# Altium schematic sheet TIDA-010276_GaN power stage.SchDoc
size 431 x 279 mm; Date: Not shown in title block; ApprovedBy: Not shown in title block; CheckedBy: Not shown in title block; Author: Not shown in title block; CompanyName: Not shown in title block; DrawnBy: Jenson Fang; Engineer: Jenson Fang; Organization: Not shown in title block; Address1: Not shown in title block; Address2: Not shown in title block; Address3: Not shown in title block; Address4: Not shown in title block; DocumentNumber: 2; Revision: Use project parameter SCH_Rev; SheetNumber: 2; SheetTotal: 6; PageSetup: Record=PageOptions¦CenterHorizontal=True¦CenterVertical=True¦PrintScale=1.00¦XCorrection=1.00¦YCorrection=1.00¦PrintKind=0¦BorderSize=5000000¦LeftOffset=0¦BottomOffset=0¦Orientation=2¦PaperLength=1000¦PaperWidth=1000¦Scale=100¦PaperSource=15¦PrintQuality=600¦MediaType=1¦DitherType=10¦PaperKind=Letter¦PrintScaleMode=1
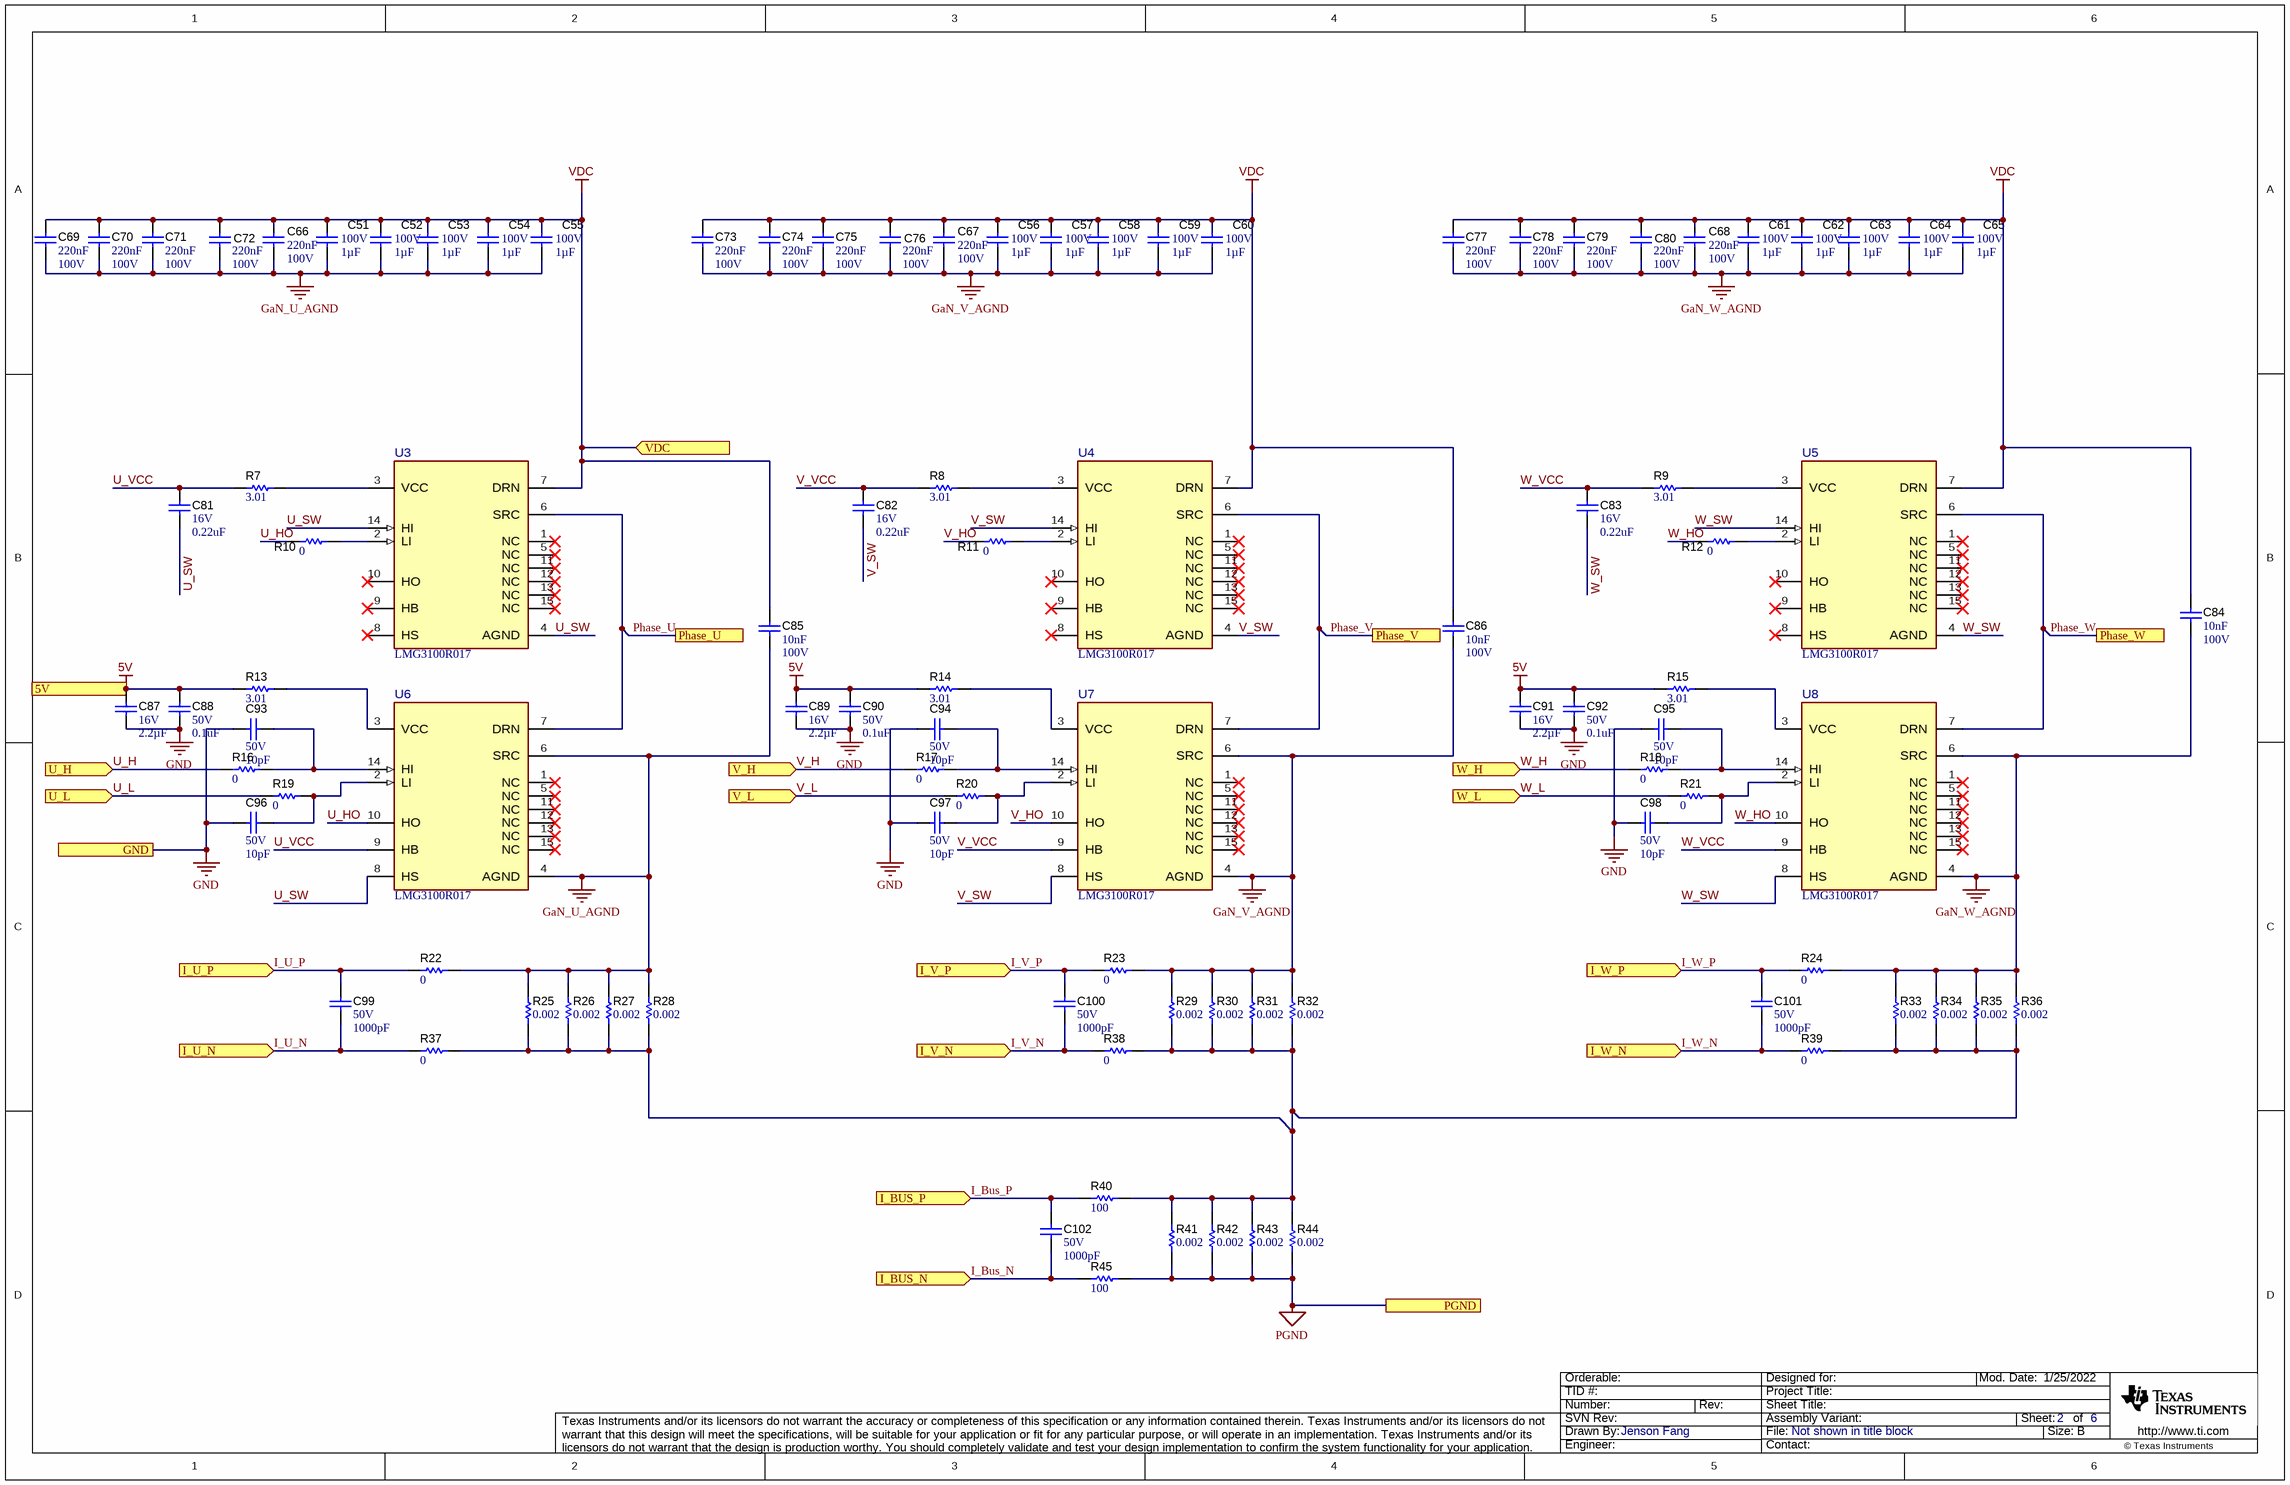
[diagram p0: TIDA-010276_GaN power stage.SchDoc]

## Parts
C51  VDC_V: 100V  ValueDisplayed: 1µF  [0805_HV]  (hidden comment: C2012X7S2A105K125AE)
C52  VDC_V: 100V  ValueDisplayed: 1µF  [0805_HV]  (hidden comment: C2012X7S2A105K125AE)
C53  VDC_V: 100V  ValueDisplayed: 1µF  [0805_HV]  (hidden comment: C2012X7S2A105K125AE)
C54  VDC_V: 100V  ValueDisplayed: 1µF  [0805_HV]  (hidden comment: C2012X7S2A105K125AE)
C55  VDC_V: 100V  ValueDisplayed: 1µF  [0805_HV]  (hidden comment: C2012X7S2A105K125AE)
C56  VDC_V: 100V  ValueDisplayed: 1µF  [0805_HV]  (hidden comment: C2012X7S2A105K125AE)
C57  VDC_V: 100V  ValueDisplayed: 1µF  [0805_HV]  (hidden comment: C2012X7S2A105K125AE)
C58  VDC_V: 100V  ValueDisplayed: 1µF  [0805_HV]  (hidden comment: C2012X7S2A105K125AE)
C59  VDC_V: 100V  ValueDisplayed: 1µF  [0805_HV]  (hidden comment: C2012X7S2A105K125AE)
C60  VDC_V: 100V  ValueDisplayed: 1µF  [0805_HV]  (hidden comment: C2012X7S2A105K125AE)
C61  VDC_V: 100V  ValueDisplayed: 1µF  [0805_HV]  (hidden comment: C2012X7S2A105K125AE)
C62  VDC_V: 100V  ValueDisplayed: 1µF  [0805_HV]  (hidden comment: C2012X7S2A105K125AE)
C63  VDC_V: 100V  ValueDisplayed: 1µF  [0805_HV]  (hidden comment: C2012X7S2A105K125AE)
C64  VDC_V: 100V  ValueDisplayed: 1µF  [0805_HV]  (hidden comment: C2012X7S2A105K125AE)
C65  VDC_V: 100V  ValueDisplayed: 1µF  [0805_HV]  (hidden comment: C2012X7S2A105K125AE)
C66  Cap_F: 220nF  VDC_V: 100V  [0603]  (hidden comment: HMK107C7224KAHTE)
C67  Cap_F: 220nF  VDC_V: 100V  [0603]  (hidden comment: HMK107C7224KAHTE)
C68  Cap_F: 220nF  VDC_V: 100V  [0603]  (hidden comment: HMK107C7224KAHTE)
C69  Cap_F: 220nF  VDC_V: 100V  [0603]  (hidden comment: HMK107C7224KAHTE)
C70  Cap_F: 220nF  VDC_V: 100V  [0603]  (hidden comment: HMK107C7224KAHTE)
C71  Cap_F: 220nF  VDC_V: 100V  [0603]  (hidden comment: HMK107C7224KAHTE)
C72  Cap_F: 220nF  VDC_V: 100V  [0603]  (hidden comment: HMK107C7224KAHTE)
C73  Cap_F: 220nF  VDC_V: 100V  [0603]  (hidden comment: HMK107C7224KAHTE)
C74  Cap_F: 220nF  VDC_V: 100V  [0603]  (hidden comment: HMK107C7224KAHTE)
C75  Cap_F: 220nF  VDC_V: 100V  [0603]  (hidden comment: HMK107C7224KAHTE)
C76  Cap_F: 220nF  VDC_V: 100V  [0603]  (hidden comment: HMK107C7224KAHTE)
C77  Cap_F: 220nF  VDC_V: 100V  [0603]  (hidden comment: HMK107C7224KAHTE)
C78  Cap_F: 220nF  VDC_V: 100V  [0603]  (hidden comment: HMK107C7224KAHTE)
C79  Cap_F: 220nF  VDC_V: 100V  [0603]  (hidden comment: HMK107C7224KAHTE)
C80  Cap_F: 220nF  VDC_V: 100V  [0603]  (hidden comment: HMK107C7224KAHTE)
C81  VDC_V: 16V  ValueDisplayed: 0.22uF  [0402]  (hidden comment: GRM155R71C224KA12D)
C82  VDC_V: 16V  ValueDisplayed: 0.22uF  [0402]  (hidden comment: GRM155R71C224KA12D)
C83  VDC_V: 16V  ValueDisplayed: 0.22uF  [0402]  (hidden comment: GRM155R71C224KA12D)
C84  Cap_F: 10nF  VDC_V: 100V  [0805_HV]  (hidden comment: GRM21BR72A103KA01L)
C85  Cap_F: 10nF  VDC_V: 100V  [0805_HV]  (hidden comment: GRM21BR72A103KA01L)
C86  Cap_F: 10nF  VDC_V: 100V  [0805_HV]  (hidden comment: GRM21BR72A103KA01L)
C87  VDC_V: 16V  Cap_F: 2.2µF  [0603]  (hidden comment: GRM188Z71C225KE43)
C88  VDC_V: 50V  ValueDisplayed: 0.1uF  [0402]  (hidden comment: GCM155R71H104KE02D)
C89  VDC_V: 16V  Cap_F: 2.2µF  [0603]  (hidden comment: GRM188Z71C225KE43)
C90  VDC_V: 50V  ValueDisplayed: 0.1uF  [0402]  (hidden comment: GCM155R71H104KE02D)
C91  VDC_V: 16V  Cap_F: 2.2µF  [0603]  (hidden comment: GRM188Z71C225KE43)
C92  VDC_V: 50V  ValueDisplayed: 0.1uF  [0402]  (hidden comment: GCM155R71H104KE02D)
C93  VDC_V: 50V  ValueDisplayed: 10pF  [0402]  (hidden comment: GRM1555C1H100JA01D)
C94  VDC_V: 50V  ValueDisplayed: 10pF  [0402]  (hidden comment: GRM1555C1H100JA01D)
C95  VDC_V: 50V  ValueDisplayed: 10pF  [0402]  (hidden comment: GRM1555C1H100JA01D)
C96  VDC_V: 50V  ValueDisplayed: 10pF  [0402]  (hidden comment: GRM1555C1H100JA01D)
C97  VDC_V: 50V  ValueDisplayed: 10pF  [0402]  (hidden comment: GRM1555C1H100JA01D)
C98  VDC_V: 50V  ValueDisplayed: 10pF  [0402]  (hidden comment: GRM1555C1H100JA01D)
C99  VDC_V: 50V  ValueDisplayed: 1000pF  [0402]  (hidden comment: GRM1555C1H102FA01D)
C100  VDC_V: 50V  ValueDisplayed: 1000pF  [0402]  (hidden comment: GRM1555C1H102FA01D)
C101  VDC_V: 50V  ValueDisplayed: 1000pF  [0402]  (hidden comment: GRM1555C1H102FA01D)
C102  VDC_V: 50V  ValueDisplayed: 1000pF  [0402]  (hidden comment: GRM1555C1H102FA01D)
R7  ValueDisplayed: 3.01  [0402]  (hidden comment: CRCW04023R01FKED)
R8  ValueDisplayed: 3.01  [0402]  (hidden comment: CRCW04023R01FKED)
R9  ValueDisplayed: 3.01  [0402]  (hidden comment: CRCW04023R01FKED)
R10  ValueDisplayed: 0  [0402]  (hidden comment: RC0402JR-070RL)
R11  ValueDisplayed: 0  [0402]  (hidden comment: RC0402JR-070RL)
R12  ValueDisplayed: 0  [0402]  (hidden comment: RC0402JR-070RL)
R13  ValueDisplayed: 3.01  [0402]  (hidden comment: CRCW04023R01FKED)
R14  ValueDisplayed: 3.01  [0402]  (hidden comment: CRCW04023R01FKED)
R15  ValueDisplayed: 3.01  [0402]  (hidden comment: CRCW04023R01FKED)
R16  ValueDisplayed: 0  [0603]  (hidden comment: PMR03EZPJ000)
R17  ValueDisplayed: 0  [0603]  (hidden comment: PMR03EZPJ000)
R18  ValueDisplayed: 0  [0603]  (hidden comment: PMR03EZPJ000)
R19  ValueDisplayed: 0  [0603]  (hidden comment: PMR03EZPJ000)
R20  ValueDisplayed: 0  [0603]  (hidden comment: PMR03EZPJ000)
R21  ValueDisplayed: 0  [0603]  (hidden comment: PMR03EZPJ000)
R22  ValueDisplayed: 0  [0603]  (hidden comment: PMR03EZPJ000)
R23  ValueDisplayed: 0  [0603]  (hidden comment: PMR03EZPJ000)
R24  ValueDisplayed: 0  [0603]  (hidden comment: PMR03EZPJ000)
R25  ValueDisplayed: 0.002  [1206]  (hidden comment: CRF1206-FZ-R002ELF)
R26  ValueDisplayed: 0.002  [1206]  (hidden comment: CRF1206-FZ-R002ELF)
R27  ValueDisplayed: 0.002  [1206]  (hidden comment: CRF1206-FZ-R002ELF)
R28  ValueDisplayed: 0.002  [1206]  (hidden comment: CRF1206-FZ-R002ELF)
R29  ValueDisplayed: 0.002  [1206]  (hidden comment: CRF1206-FZ-R002ELF)
R30  ValueDisplayed: 0.002  [1206]  (hidden comment: CRF1206-FZ-R002ELF)
R31  ValueDisplayed: 0.002  [1206]  (hidden comment: CRF1206-FZ-R002ELF)
R32  ValueDisplayed: 0.002  [1206]  (hidden comment: CRF1206-FZ-R002ELF)
R33  ValueDisplayed: 0.002  [1206]  (hidden comment: CRF1206-FZ-R002ELF)
R34  ValueDisplayed: 0.002  [1206]  (hidden comment: CRF1206-FZ-R002ELF)
R35  ValueDisplayed: 0.002  [1206]  (hidden comment: CRF1206-FZ-R002ELF)
R36  ValueDisplayed: 0.002  [1206]  (hidden comment: CRF1206-FZ-R002ELF)
R37  ValueDisplayed: 0  [0603]  (hidden comment: PMR03EZPJ000)
R38  ValueDisplayed: 0  [0603]  (hidden comment: PMR03EZPJ000)
R39  ValueDisplayed: 0  [0603]  (hidden comment: PMR03EZPJ000)
R40  ValueDisplayed: 100  [0402]  (hidden comment: CRCW0402100RJNED)
R41  ValueDisplayed: 0.002  [1206]  (hidden comment: CRF1206-FZ-R002ELF)
R42  ValueDisplayed: 0.002  [1206]  (hidden comment: CRF1206-FZ-R002ELF)
R43  ValueDisplayed: 0.002  [1206]  (hidden comment: CRF1206-FZ-R002ELF)
R44  ValueDisplayed: 0.002  [1206]  (hidden comment: CRF1206-FZ-R002ELF)
R45  ValueDisplayed: 100  [0402]  (hidden comment: CRCW0402100RJNED)
U3  LMG3100R017  [VBE0015A-MFG]
U4  LMG3100R017  [VBE0015A-MFG]
U5  LMG3100R017  [VBE0015A-MFG]
U6  LMG3100R017  [VBE0015A-MFG]
U7  LMG3100R017  [VBE0015A-MFG]
U8  LMG3100R017  [VBE0015A-MFG]

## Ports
5V, GND, I_BUS_N (in), I_BUS_P (in), I_U_N (in), I_U_P (in), I_V_N (in), I_V_P (in), I_W_N (in), I_W_P (in), PGND, Phase_U, Phase_V, Phase_W, U_H (in), U_L (in), V_H (in), V_L (in), VDC (in), W_H (in), W_L (in)

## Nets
5V: C87.1 C88.1 C89.1 C90.1 C91.1 C92.1 R13.1 R14.1 R15.1 ; port 5V
GaN_U_AGND: C51.2 C52.2 C53.2 C54.2 C55.2 C66.2 C69.2 C70.2 C71.2 C72.2 C85.2 R22.1 R25.2 R26.2 R27.2 R28.2 U6.4(AGND) U6.6(SRC)
GaN_V_AGND: C56.2 C57.2 C58.2 C59.2 C60.2 C67.2 C73.2 C74.2 C75.2 C76.2 C86.2 R23.1 R29.2 R30.2 R31.2 R32.2 U7.4(AGND) U7.6(SRC)
GaN_W_AGND: C61.2 C62.2 C63.2 C64.2 C65.2 C68.2 C77.2 C78.2 C79.2 C80.2 C84.2 R24.1 R33.2 R34.2 R35.2 R36.2 U8.4(AGND) U8.6(SRC)
GND: C87.2 C88.2 C89.2 C90.2 C91.2 C92.2 C93.2 C94.2 C95.2 C96.2 C97.2 C98.2 ; port GND
PGND: R41.1 R42.1 R43.1 R44.1 R45.2 ; port PGND
VDC: C51.1 C52.1 C53.1 C54.1 C55.1 C56.1 C57.1 C58.1 C59.1 C60.1 C61.1 C62.1 C63.1 C64.1 C65.1 C66.1 C67.1 C68.1 C69.1 C70.1 C71.1 C72.1 C73.1 C74.1 C75.1 C76.1 C77.1 C78.1 C79.1 C80.1 C84.1 C85.1 C86.1 U3.7(DRN) U4.7(DRN) U5.7(DRN) ; port VDC
I_Bus_N: C102.2 R45.1 ; port I_BUS_N
I_Bus_P: C102.1 R40.1 ; port I_BUS_P
I_U_N: C99.2 R37.2 ; port I_U_N
I_U_P: C99.1 R22.2 ; port I_U_P
I_V_N: C100.2 R38.2 ; port I_V_N
I_V_P: C100.1 R23.2 ; port I_V_P
I_W_N: C101.2 R39.2 ; port I_W_N
I_W_P: C101.1 R24.2 ; port I_W_P
Phase_U: U3.6(SRC) U6.7(DRN) ; port Phase_U
Phase_V: U4.6(SRC) U7.7(DRN) ; port Phase_V
Phase_W: U5.6(SRC) U8.7(DRN) ; port Phase_W
U_H: R16.2 ; port U_H
U_HO: R10.1 U6.10(HO)
U_L: R19.2 ; port U_L
U_SW: C81.2 U3.4(AGND) U3.14(HI) U6.8(HS)
U_VCC: C81.1 R7.1 U6.9(HB)
V_H: R17.2 ; port V_H
V_HO: R11.1 U7.10(HO)
V_L: R20.2 ; port V_L
V_SW: C82.2 U4.4(AGND) U4.14(HI) U7.8(HS)
V_VCC: C82.1 R8.1 U7.9(HB)
W_H: R18.2 ; port W_H
W_HO: R12.1 U8.10(HO)
W_L: R21.2 ; port W_L
W_SW: C83.2 U5.4(AGND) U5.14(HI) U8.8(HS)
W_VCC: C83.1 R9.1 U8.9(HB)
NetC93_1: C93.1 R16.1 U6.14(HI)
NetC94_1: C94.1 R17.1 U7.14(HI)
NetC95_1: C95.1 R18.1 U8.14(HI)
NetC96_1: C96.1 R19.1 U6.2(LI)
NetC97_1: C97.1 R20.1 U7.2(LI)
NetC98_1: C98.1 R21.1 U8.2(LI)
NetR7_2: R7.2 U3.3(VCC)
NetR8_2: R8.2 U4.3(VCC)
NetR9_2: R9.2 U5.3(VCC)
NetR10_2: R10.2 U3.2(LI)
NetR11_2: R11.2 U4.2(LI)
NetR12_2: R12.2 U5.2(LI)
NetR13_2: R13.2 U6.3(VCC)
NetR14_2: R14.2 U7.3(VCC)
NetR15_2: R15.2 U8.3(VCC)
NetR25_1: R25.1 R26.1 R27.1 R28.1 R29.1 R30.1 R31.1 R32.1 R33.1 R34.1 R35.1 R36.1 R37.1 R38.1 R39.1 R40.2 R41.2 R42.2 R43.2 R44.2

Not connected (* = marked no-connect by the designer): U3 1(NC)* 5(NC)* 8(HS)* 9(HB)* 10(HO)* 11(NC)* 12(NC)* 13(NC)* 15(NC)*; U4 1(NC)* 5(NC)* 8(HS)* 9(HB)* 10(HO)* 11(NC)* 12(NC)* 13(NC)* 15(NC)*; U5 1(NC)* 5(NC)* 8(HS)* 9(HB)* 10(HO)* 11(NC)* 12(NC)* 13(NC)* 15(NC)*; U6 1(NC)* 5(NC)* 11(NC)* 12(NC)* 13(NC)* 15(NC)*; U7 1(NC)* 5(NC)* 11(NC)* 12(NC)* 13(NC)* 15(NC)*; U8 1(NC)* 5(NC)* 11(NC)* 12(NC)* 13(NC)* 15(NC)*

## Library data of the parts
C51-C65 = CMP-0750059-1: CAP, CERM, 1 µF, 100 V,+/- 10%, X7S, 0805; Manufacturer: TDK; TaMax_C: 125°C; SizeAreaWB_mm2: 6.75; SizeY_mm: 1.25; Green_REACh: Incomplete; TaMin_C: -55°C; Cap_Case: 0805; SizeZ_mm: 1.45; U/M: EA; SizeX_mm: 2; Polarized: N; Green_Lifecycle: Active; SizeArea_mm2: 2.5; Value: 1uF; AEC Category: Q200
C66-C80 = CMP-0077894-3: CAP, CERM, 0.22 µF, 100 V,+/- 10%, X7S, AEC-Q200 Grade 1, 0603; Manufacturer: Taiyo Yuden; TaMin_C: -55°C; Polarized: N; SizeAreaWB_mm2: 4.68; U/M: EA; Value: 0.22uF; TaMax_C: 125°C; SizeZ_mm: 1.0; SizeX_mm: 1.6; SizeY_mm: 0.8; SizeArea_mm2: 1.28; AEC Qualified: Y; AEC Category: Q200; ValueDisplayed: 0.22µF; AEC Grade: 1
C81-C83 = CMP-0006648-1: CAP, CERM, 0.22 uF, 16 V, +/- 10%, X7R, 0402; Manufacturer: MuRata; TaMin_C: -55°C; Polarized: N; SizeAreaWB_mm2: 3; Value1: Unknown; U/M: EA; Value: 0.22uF; TaMax_C: 125°C; SizeZ_mm: 0.6; SizeX_mm: 1; SizeY_mm: 0.5; Cap_F: 220nF; AEC Category: Q200
C84-C86 = CMP-0008361-2: CAP, CERM, 0.01 uF, 100 V, +/- 10%, X7R, 0805; Manufacturer: MuRata; TaMin_C: -55°C; Polarized: N; SizeAreaWB_mm2: 6.75; Value1: Unknown; U/M: EA; Value: 0.01uF; TaMax_C: 125°C; SizeZ_mm: 1.45; SizeX_mm: 2; SizeY_mm: 1.25; Cap_Case: 0805; SizeArea_mm2: 2.5; AEC Category: Q200
C87 C89 C91 = CMP-0007499-1: CAP, CERM, 2.2 uF, 16 V, +/- 10%, X7R, 0603; Manufacturer: MuRata; TaMin_C: -55°C; Polarized: N; SizeAreaWB_mm2: 4.68; Value1: Unknown; U/M: EA; Value: 2.2uF; TaMax_C: 125°C; SizeZ_mm: 1; SizeX_mm: 1.6; SizeY_mm: 0.8; SizeArea_mm2: 1.28; AEC Category: Q200
C88 C90 C92 = CMP-0006356-2: CAP, CERM, 0.1 uF, 50 V, +/- 10%, X7R, AEC-Q200 Grade 1, 0402; Manufacturer: MuRata; TaMin_C: -55°C; Polarized: N; SizeAreaWB_mm2: 3; Value1: Unknown; U/M: EA; Value: 0.1uF; TaMax_C: 125°C; SizeZ_mm: 0.6; SizeX_mm: 1; SizeY_mm: 0.5; AEC Qualified: Y; Cap_F: 100nF; AEC Category: Q200
C93-C98 = CMP-0006408-2: CAP, CERM, 10 pF, 50 V, +/- 5%, C0G/NP0, 0402; Manufacturer: MuRata; TaMin_C: -55°C; Polarized: N; SizeAreaWB_mm2: 3; Value1: Unknown; U/M: EA; Value: 10pF; TaMax_C: 125°C; SizeZ_mm: 0.6; SizeX_mm: 1; SizeY_mm: 0.5; AEC Category: Q200
C99-C102 = CMP-0006411-2: CAP, CERM, 1000 pF, 50 V, +/- 1%, C0G/NP0, 0402; Manufacturer: MuRata; TaMin_C: -55°C; Polarized: N; SizeAreaWB_mm2: 3; Value1: Unknown; U/M: EA; Value: 1000pF; TaMax_C: 125°C; SizeZ_mm: 0.6; SizeX_mm: 1; SizeY_mm: 0.5; Cap_F: 1nF; AEC Category: Q200
R7-R9 R13-R15 = CMP-0026353-2: RES, 3.01, 1%, 0.063 W, AEC-Q200 Grade 0, 0402; Manufacturer: Vishay-Dale; Power_W: 63mW; TempCo: 100 ppm/C; Value_Code: 3R01; Value: 3.01; EIA_Code: E96; SizeX_mm: 1; SizeY_mm: 0.5; SizeZ_mm: 0.6; Value2: 0.063W; AEC Qualified: Y; VDC_V: 50V; AEC Category: Q200; AEC Grade: 0
R10-R12 = CMP-0027004-2: RES, 0, 5%, 0.063 W, 0402; Manufacturer: Yageo America; Power_W: 63mW; TempCo: 200 ppm/C; Value_Code: 0000; U/M: EA; Value: 0; EIA_Code: E24; SizeX_mm: 1; SizeY_mm: 0.5; SizeZ_mm: 0.6; Value2: 0.063W; VDC_V: 50V; AEC Category: Q200
R16-R24 R37-R39 = CMP-0086358-1: RES, 0, 0%, 0.25 W, AEC-Q200 Grade 0, 0603; Manufacturer: Rohm; Power_W: 250mW; SizeZ_mm: 1; SizeArea_mm2: 1.28; Value2: 0.25W; SizeAreaWB_mm2: 4.68; Value_Code: 0000; Value: 0; AEC Qualified: Y; AEC Category: Q200; SizeX_mm: 1.6; SizeY_mm: 0.8
R25-R36 R41-R44 = CMP-0078822-1: RES, 0.002, 1%, 1 W, AEC-Q200 Grade 0, 1206; Manufacturer: Bourns; Value_Code: 2L000; SizeArea_mm2: 5.12; AEC Qualified: Y; AEC Category: Q200; Res_ohm: 2m; Value: 0.002; SizeZ_mm: 1.35; TempCo: 50 ppm/C; AEC Grade: 0; SizeY_mm: 1.6; Power_W: 1W; SizeX_mm: 3.2
R40 R45 = CMP-0026824-3: RES, 100, 5%, 0.063 W, AEC-Q200 Grade 0, 0402; Manufacturer: Vishay-Dale; Power_W: 63mW; TempCo: 200 ppm/C; Value_Code: 100R; Value: 100; EIA_Code: E24; SizeX_mm: 1; SizeY_mm: 0.5; SizeZ_mm: 0.6; Value2: 0.063W; AEC Qualified: Y; VDC_V: 50V; AEC Category: Q200; AEC Grade: 0
U3-U8 = CMP-0037654-1: 100-V, 64-A GaN with Integrated Driver; Manufacturer: Texas Instruments; SizeZ_mm: 0.85mm; AEC Qualified: No; Max Supply Voltage: 5.25V; Min Supply Voltage: 4.75V; Nominal Supply Current: 3mA; Number Of Drivers: 1; Propagation Delay: 55ns; Standoff Height: 0mm; TJmax_C: +125°C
